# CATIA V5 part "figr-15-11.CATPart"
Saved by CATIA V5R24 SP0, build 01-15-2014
Part number: Part1
Bounding box of the stored display mesh (mm): x -50 to 50, y -32.5 to 33.5, z -52 to 1
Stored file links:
  D:\KAVITA\CATIA V5-6R2014 Project_ Kavita\CATIA V5-6R2014_partfiles\Partfiles\c15_catia_v5-6r2014_prt\figr-15-11.CATPart
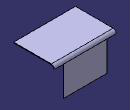
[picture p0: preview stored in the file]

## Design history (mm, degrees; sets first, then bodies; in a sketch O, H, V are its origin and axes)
SheetMetalParameters1: Thickness 1, BendRadius 4, KFactor 0.475772 {= log(min(100,max(20*SheetMetalParameters1.BendRadius,SheetMetalParameters1.Thickness)/SheetMetalParameters1.Thickness))/log(100)/2}, ReliefRadialLength 4, ReliefAxialLength 4, MinimumBendRadius 0
Body1 (main body)
  Sketch1 on xy-plane, origin (0, 0, 0), H (1, 0, 0), V (0, 1, 0)
    line L1 (-50, 32.5) -> (50, 32.5)
    line L2 (50, 32.5) -> (50, -32.5)
    line L3 (50, -32.5) -> (-50, -32.5)
    line L4 (-50, -32.5) -> (-50, 32.5)
    length L1 = 100
    length L2 = 65
    horizontal: L1 H, L3 H
    vertical: L2 V, L4 V
    symmetry: L4 L2 V, L1 L3 H
  Wall1: Thickness 1, Profile Sketch1
  d_NewWallOnEdge1: NewWallOnEdge_Edge edge [face of Wall1 | face of Wall1], NewWallOnEdge_Length 53, NewWallOnEdge_HeightLimitOffset 0, NewWallOnEdge_WidthOffset1 -15, NewWallOnEdge_WidthOffset2 -15, NewWallOnEdge_Angle 90, NewWallOnEdge_BendRadiusValue 4 {= SheetMetalParameters1.BendRadius}, NewWallOnEdge_BendTable SheetMetalParameters1, KFacteur 0.475772 {= log(min(100,max(20*d_NewWallOnEdge1.Radius,SheetMetalParameters1.Thickness)/SheetMetalParameters1.Thickness))/log(100)/2}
